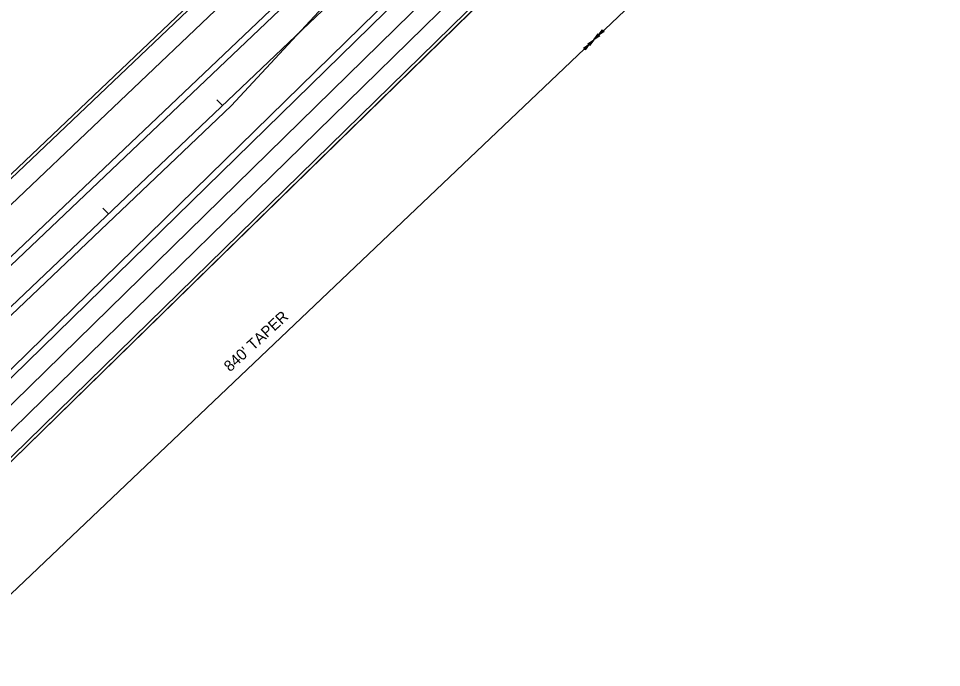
# Model space of a CAD drawing. Extents: x 2389099 to 2405615, y 552200 to 573532.
# Drawn here: x 2397239 to 2397826, y 558661 to 559073 of the extents above; entities that cross this region are included whole.
import ezdxf

# ---------------------------------------------------------------- set-up
doc = ezdxf.new("R2010")
doc.units = 0
for name, color, linetype in [('Prop Cable Guiderail Double Face', 7, 'Continuous'), ('Prop Cable Guiderail Single Face', 7, 'Continuous'), ('Prop Conc Expressway Gutter', 7, 'Continuous'), ('Prop Dimension', 7, 'Continuous'), ('Prop Dimension Text', 7, 'Continuous'), ('Prop EOT', 7, 'Continuous'), ('Prop Guardrail', 7, 'Continuous'), ('Prop Horizontal Alignment', 7, 'Continuous'), ('Prop Horizontal Alignment Tick Small', 7, 'Continuous'), ('Prop Lane Lines', 7, 'Continuous')]:
    doc.layers.add(name, color=color, linetype=linetype)

msp = doc.modelspace()

# ---------------------------------------------------------------- linework, layer by layer
at = {"layer": 'Prop Cable Guiderail Double Face'}
msp.add_line((2397578.98, 559238.42), (2397374.65, 559017.94), dxfattribs=at)
at = {"layer": 'Prop Cable Guiderail Single Face'}
msp.add_line((2396605.31, 558286.52), (2397374.65, 559017.94), dxfattribs=at)
at = {"layer": 'Prop Conc Expressway Gutter'}
for p, q in [((2397067.44, 558812.79), (2397560.28, 559281.35)), ((2397717.75, 559267.14), (2396556.62, 558131.22))]:
    msp.add_line(p, q, dxfattribs=at)
at = {"layer": 'Prop Dimension'}
msp.add_line((2397199.35, 558674.04), (2397808.13, 559252.82), dxfattribs=at)
for points in [[(2397611.84, 559065.18), (2397608.05, 559062.64), (2397610.78, 559066.33), (2397610.91, 559065.36)], [(2397601.39, 559057.38), (2397605.18, 559059.92), (2397602.46, 559056.22), (2397602.32, 559057.19)], [(2397608.98, 559062.45), (2397605.18, 559059.92), (2397607.91, 559063.61), (2397608.05, 559062.64)], [(2397598.53, 559054.66), (2397602.32, 559057.19), (2397599.59, 559053.5), (2397599.46, 559054.47)]]:
    msp.add_lwpolyline(points, close=True, dxfattribs=at)
at = {"layer": 'Prop EOT'}
for p, q in [((2397075.71, 558804.1), (2398839.56, 560481.03)), ((2397092.24, 558786.7), (2398856.1, 560463.63)), ((2396531.69, 558157.19), (2397732.72, 559332.14)), ((2397749.26, 559314.75), (2396548.23, 558139.8)), ((2397066.06, 558814.24), (2397558.9, 559282.8)), ((2397095, 558783.8), (2397618.4, 559281.41)), ((2397719.15, 559265.71), (2396558.02, 558129.79)), ((2396528.9, 558160.05), (2397504.06, 559114.05))]:
    msp.add_line(p, q, dxfattribs=at)
at = {"layer": 'Prop Guardrail'}
for p, q in [((2397558.9, 559282.8), (2397066.06, 558814.24)), ((2396558.02, 558129.79), (2397719.15, 559265.71))]:
    msp.add_line(p, q, dxfattribs=at)
at = {"layer": 'Prop Horizontal Alignment'}
msp.add_line((2396449.76, 558144.15), (2398871.95, 560446.96), dxfattribs=at)
at = {"layer": 'Prop Horizontal Alignment Tick Small'}
for p, q in [((2397369, 559018.08), (2397365.55, 559021.71)), ((2397296.52, 558949.18), (2397293.08, 558952.8))]:
    msp.add_line(p, q, dxfattribs=at)
at = {"layer": 'Prop Lane Lines'}
for p, q in [((2397075.71, 558804.1), (2398839.56, 560481.03)), ((2397601.13, 559186.62), (2396539.96, 558148.5))]:
    msp.add_line(p, q, dxfattribs=at)

# ---------------------------------------------------------------- texts
at = {"layer": 'Prop Dimension Text'}
msp.add_text("840' TAPER", height=7, rotation=42.59894, dxfattribs=at).set_placement((2397373.89, 558848.36))

doc.saveas('drawing.dxf')
